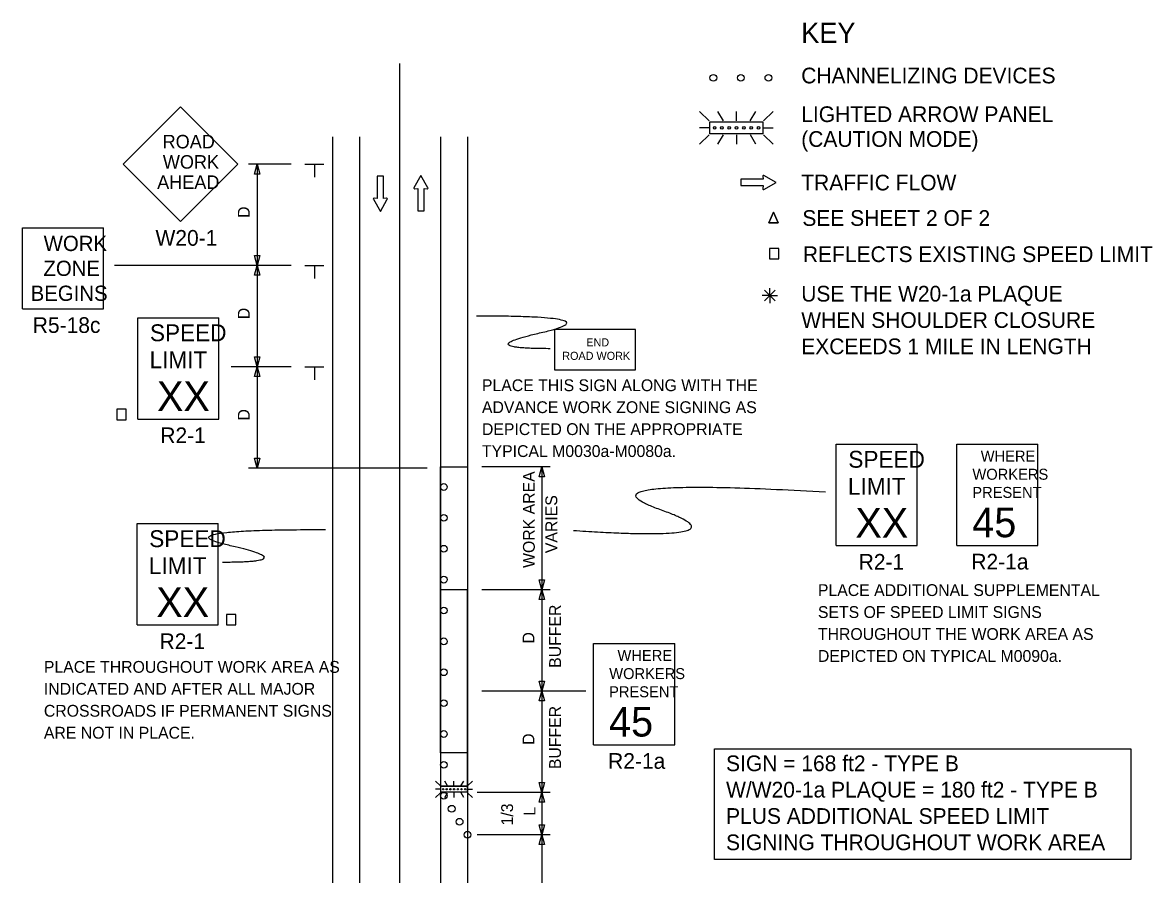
# Model space of a CAD drawing. Extents: x 16750 to 18472, y 7218 to 8205.
# Drawn here: x 16760 to 17429, y 7700 to 8205 of the extents above; entities that cross this region are included whole.
import ezdxf

# ---------------------------------------------------------------- set-up
doc = ezdxf.new("R2010")
doc.units = 0
for name, color, linetype in [('Level 6', 7, 'Continuous'), ('MT_SCRATCH_LEVEL_E', 7, 'Continuous'), ('PAVT_EDGE_EX', 7, 'Continuous'), ('TRAFFIC_SIGNS_PR', 7, 'Continuous'), ('TYPICAL_TEXT_DIMEN_EX', 7, 'Continuous'), ('TYPICAL_TEXT_DIMEN_PR', 7, 'Continuous')]:
    doc.layers.add(name, color=color, linetype=linetype)

msp = doc.modelspace()

# ---------------------------------------------------------------- linework, layer by layer
at = {"layer": 'Level 6'}
for p, q in [((17313.03, 7955.14), (17361.03, 7955.14)), ((17313.03, 7895.14), (17313.03, 7955.14)), ((17361.03, 7895.14), (17361.03, 7955.14)), ((17313.03, 7895.14), (17361.03, 7895.14)), ((17097.89, 7837.09), (17145.89, 7837.09)), ((17097.89, 7777.09), (17097.89, 7837.09)), ((17145.89, 7777.09), (17145.89, 7837.09)), ((17097.89, 7777.09), (17145.89, 7777.09))]:
    msp.add_line(p, q, dxfattribs=at)
for points in [[(17204.47, 8092.37), (17201.67, 8086.2)], [(17201.67, 8086.2), (17204.47, 8092.37)], [(17207.26, 8086.2), (17204.47, 8092.37)], [(17204.47, 8092.37), (17207.26, 8086.2)], [(17201.67, 8086.2), (17207.26, 8086.2)], [(17207.26, 8086.2), (17201.67, 8086.2)]]:
    msp.add_lwpolyline(points, dxfattribs=at)
for points in [[(17202.01, 8064.76), (17207.6, 8064.76), (17207.6, 8070.93), (17202.01, 8070.93)], [(16815.46, 7969.56), (16821.05, 7969.56), (16821.05, 7975.73), (16815.46, 7975.73)], [(16880.44, 7848.01), (16886.04, 7848.01), (16886.04, 7854.18), (16880.44, 7854.18)]]:
    msp.add_lwpolyline(points, close=True, dxfattribs=at)
at = {"layer": 'MT_SCRATCH_LEVEL_E'}
for p, q in [((16973.41, 8113.8), (16969.67, 8113.8)), ((16969.67, 8113.8), (16969.67, 8100.54)), ((16973.41, 8113.8), (16969.67, 8113.8)), ((16969.67, 8113.8), (16969.67, 8100.54)), ((16973.41, 8100.54), (16973.41, 8113.8)), ((16973.41, 8100.54), (16973.41, 8113.8)), ((16995.57, 8114.17), (16991.46, 8106.93)), ((16995.57, 8114.17), (16991.46, 8106.93)), ((16999.72, 8106.93), (16995.57, 8114.17)), ((16999.72, 8106.93), (16995.57, 8114.17)), ((17198.4, 8111.93), (17185.15, 8111.93)), ((17185.15, 8111.93), (17185.15, 8108.19)), ((17198.4, 8111.93), (17185.15, 8111.93)), ((17185.15, 8111.93), (17185.15, 8108.19)), ((17198.09, 8113.71), (17198.4, 8111.93)), ((17198.09, 8113.71), (17198.4, 8111.93)), ((17206.01, 8110.08), (17198.77, 8114.19)), ((17206.01, 8110.08), (17198.77, 8114.19)), ((16991.94, 8106.24), (16993.72, 8106.56)), ((16991.94, 8106.24), (16993.72, 8106.56)), ((16993.72, 8106.56), (16993.72, 8093.3)), ((16993.72, 8106.56), (16993.72, 8093.3)), ((16997.46, 8093.3), (16997.46, 8106.56)), ((16997.46, 8106.56), (16999.24, 8106.24)), ((16997.46, 8093.3), (16997.46, 8106.56)), ((16997.46, 8106.56), (16999.24, 8106.24)), ((17185.15, 8108.19), (17198.4, 8108.19)), ((17185.15, 8108.19), (17198.4, 8108.19)), ((17198.4, 8108.19), (17198.09, 8106.41)), ((17198.4, 8108.19), (17198.09, 8106.41)), ((17198.77, 8105.93), (17206.01, 8110.08)), ((17198.77, 8105.93), (17206.01, 8110.08)), ((16967.42, 8100.17), (16971.56, 8092.93)), ((16967.42, 8100.17), (16971.56, 8092.93)), ((16969.67, 8100.54), (16967.9, 8100.85)), ((16969.67, 8100.54), (16967.9, 8100.85)), ((16971.56, 8092.93), (16975.67, 8100.17)), ((16971.56, 8092.93), (16975.67, 8100.17)), ((16975.19, 8100.85), (16973.41, 8100.54)), ((16975.19, 8100.85), (16973.41, 8100.54)), ((16993.72, 8093.3), (16997.46, 8093.3)), ((16993.72, 8093.3), (16997.46, 8093.3))]:
    msp.add_line(p, q, dxfattribs=at)
for centre, start, end in [((17198.55, 8113.78), 60.42484, 189.96381), ((17198.55, 8113.78), 60.42484, 189.96381), ((16991.87, 8106.7), 150.42484, 279.96381), ((16991.87, 8106.7), 150.42484, 279.96381), ((16999.31, 8106.7), 260.03619, 29.77312), ((16999.31, 8106.7), 260.03619, 29.77312), ((17198.55, 8106.34), 170.03619, 299.77312), ((17198.55, 8106.34), 170.03619, 299.77312), ((16967.82, 8100.39), 80.03619, 209.77312), ((16967.82, 8100.39), 80.03619, 209.77312), ((16975.27, 8100.39), 330.42484, 99.96381), ((16975.27, 8100.39), 330.42484, 99.96381)]:
    msp.add_arc(centre, 0.463, start, end, dxfattribs=at)
at = {"layer": 'PAVT_EDGE_EX'}
for p, q in [((16983.15, 7383.56), (16983.15, 8180.56)), ((16943.15, 8137.01), (16943.15, 7401.86)), ((16959.15, 8137.01), (16959.15, 7401.86)), ((17007.15, 8137.01), (17007.15, 7401.86)), ((17023.15, 8137.01), (17023.15, 7401.86)), ((17007.15, 7772.28), (17007.15, 7941.6)), ((17007.15, 7941.6), (17023.15, 7941.6)), ((17023.15, 7941.6), (17023.15, 7772.28)), ((17023.15, 7868.84), (17007.15, 7868.84)), ((17007.15, 7868.84), (17007.15, 7752.58)), ((17023.15, 7752.58), (17023.15, 7868.84)), ((17023.15, 7772.28), (17007.15, 7772.28)), ((17007.15, 7752.58), (17023.15, 7752.58))]:
    msp.add_line(p, q, dxfattribs=at)
for points in [[(16983.15, 8101.86), (16983.15, 8126.86)], [(16983.15, 8001.86), (16983.15, 8026.86)], [(16983.15, 7901.86), (16983.15, 7926.86)], [(16983.15, 7801.86), (16983.15, 7826.86)], [(16983.15, 7701.86), (16983.15, 7726.86)]]:
    msp.add_lwpolyline(points, dxfattribs=at)
at = {"layer": 'TRAFFIC_SIGNS_PR'}
for p, q in [((16853.15, 8154.77), (16819.21, 8120.83)), ((16887.09, 8120.83), (16853.15, 8154.77)), ((17160.6, 8152.13), (17166.24, 8146.49)), ((17174.78, 8146.49), (17171.52, 8152.13)), ((17182.41, 8146.49), (17182.41, 8152.13)), ((17190.68, 8146.49), (17193.93, 8152.13)), ((17198.58, 8146.49), (17204.22, 8152.13)), ((17166.24, 8142.43), (17160.6, 8142.43)), ((17160.6, 8132.73), (17166.24, 8138.36)), ((17169.51, 8142.43), (17169.51, 8142.43)), ((17171.47, 8132.72), (17174.72, 8138.36)), ((17173.86, 8142.43), (17173.86, 8142.43)), ((17178.21, 8142.43), (17178.21, 8142.43)), ((17182.41, 8138.36), (17182.41, 8132.72)), ((17182.56, 8142.43), (17182.56, 8142.43)), ((17186.9, 8142.43), (17186.9, 8142.43)), ((17193.98, 8132.72), (17190.73, 8138.36)), ((17191.25, 8142.43), (17191.25, 8142.43)), ((17195.6, 8142.43), (17195.6, 8142.43)), ((17198.58, 8142.43), (17204.22, 8142.43)), ((17198.58, 8138.36), (17204.22, 8132.72)), ((16819.21, 8120.83), (16853.15, 8086.88)), ((16853.15, 8086.88), (16887.09, 8120.83)), ((16759.63, 8035.25), (16759.63, 8083.25)), ((16759.63, 8083.25), (16807.63, 8083.25)), ((16807.63, 8035.25), (16807.63, 8083.25)), ((16759.63, 8035.25), (16807.63, 8035.25)), ((16827.86, 8029.97), (16875.86, 8029.97)), ((16827.86, 7969.97), (16827.86, 8029.97)), ((16875.86, 7969.97), (16875.86, 8029.97)), ((16827.86, 7969.97), (16875.86, 7969.97)), ((17241.54, 7955.03), (17289.54, 7955.03)), ((17241.54, 7895.03), (17241.54, 7955.03)), ((17289.54, 7895.03), (17289.54, 7955.03)), ((17009.15, 7929.7), (17009.15, 7929.7)), ((17009.15, 7911.41), (17009.15, 7911.41)), ((16827.43, 7908.01), (16875.43, 7908.01)), ((16827.43, 7848.01), (16827.43, 7908.01)), ((16875.43, 7848.01), (16875.43, 7908.01)), ((17009.15, 7893.13), (17009.15, 7893.13)), ((17241.54, 7895.03), (17289.54, 7895.03)), ((17009.15, 7874.84), (17009.15, 7874.84)), ((16827.43, 7848.01), (16875.43, 7848.01)), ((17023.15, 7772.28), (17007.15, 7772.28)), ((17004.26, 7755.53), (17007.08, 7752.71)), ((17007.08, 7750.68), (17004.26, 7750.68)), ((17023.15, 7752.58), (17007.15, 7752.58)), ((17008.72, 7750.68), (17008.72, 7750.68)), ((17011.35, 7752.71), (17009.72, 7755.53)), ((17010.9, 7750.68), (17010.9, 7750.68)), ((17013.07, 7750.68), (17013.07, 7750.68)), ((17015.17, 7752.71), (17015.17, 7755.53)), ((17015.24, 7750.68), (17015.24, 7750.68)), ((17017.42, 7750.68), (17017.42, 7750.68)), ((17019.3, 7752.71), (17020.93, 7755.53)), ((17019.59, 7750.68), (17019.59, 7750.68)), ((17021.76, 7750.68), (17021.76, 7750.68)), ((17023.25, 7752.71), (17026.08, 7755.53)), ((17023.25, 7750.68), (17026.08, 7750.68)), ((17004.26, 7745.83), (17007.08, 7748.64)), ((17009.7, 7745.82), (17011.33, 7748.64)), ((17015.17, 7748.64), (17015.17, 7745.82)), ((17020.96, 7745.82), (17019.33, 7748.64)), ((17023.25, 7748.64), (17026.08, 7745.82))]:
    msp.add_line(p, q, dxfattribs=at)
for points in [[(17198.12, 8138.83), (17166.7, 8138.83), (17166.7, 8146.03), (17198.12, 8146.03)], [(17074.78, 7999.07), (17122.78, 7999.07), (17122.78, 8023.07), (17074.78, 8023.07)], [(17023.02, 7748.88), (17007.32, 7748.88), (17007.32, 7752.48), (17023.02, 7752.48)]]:
    msp.add_lwpolyline(points, close=True, dxfattribs=at)
for centre, radius in [((17168.8, 8172), 2), ((17185.1, 8172), 2), ((17201.4, 8172), 2), ((17169.55, 8142.43), 0.758), ((17173.86, 8142.43), 0.758), ((17178.21, 8142.43), 0.758), ((17182.55, 8142.43), 0.758), ((17186.9, 8142.43), 0.758), ((17191.25, 8142.43), 0.758), ((17195.6, 8142.43), 0.758), ((17009.15, 7929.7), 2), ((17009.15, 7911.41), 2), ((17009.15, 7893.13), 2), ((17009.15, 7874.84), 2), ((17009.15, 7856.55), 2), ((17009.15, 7838.27), 2), ((17009.15, 7819.98), 2), ((17009.15, 7801.7), 2), ((17009.15, 7783.41), 2), ((17009.15, 7765.13), 2), ((17008.74, 7750.68), 0.379), ((17010.89, 7750.68), 0.379), ((17013.07, 7750.68), 0.379), ((17015.24, 7750.68), 0.379), ((17017.42, 7750.68), 0.379), ((17019.59, 7750.68), 0.379), ((17021.76, 7750.68), 0.379), ((17009.14, 7746.84), 2), ((17009.15, 7746.84), 2), ((17013.81, 7739.14), 2), ((17018.48, 7731.45), 2), ((17023.15, 7723.75), 2)]:
    msp.add_circle(centre, radius, dxfattribs=at)
for points in [[(17072.14, 8011.62), (17024.9, 8011.62), (17109.92, 8030.96), (17028.44, 8030.96)], [(17085.99, 7903.97), (17191.91, 7896.9), (17082.67, 7935.63), (17235.15, 7926.81)], [(16877.98, 7885.25), (16925.21, 7885.25), (16840.19, 7904.6), (16939, 7904.48)]]:
    msp.add_open_spline(points, degree=2, dxfattribs=at)
at = {"layer": 'TYPICAL_TEXT_DIMEN_PR'}
for p, q in [((16918.8, 8120.93), (16893.52, 8120.93)), ((16896.95, 8115.07), (16898.52, 8120.93)), ((16898.52, 8120.93), (16900.09, 8115.07)), ((16898.52, 8120.93), (16898.52, 8060.93)), ((16926.84, 8120.93), (16938.09, 8120.93)), ((16932.46, 8120.93), (16932.46, 8113.15)), ((16898.52, 8115.07), (16896.95, 8115.07)), ((16900.09, 8115.07), (16898.52, 8115.07)), ((16898.52, 8060.93), (16896.95, 8066.79)), ((16896.95, 8066.79), (16898.52, 8066.79)), ((16898.52, 8066.79), (16900.09, 8066.79)), ((16900.09, 8066.79), (16898.52, 8060.93)), ((16918.8, 8060.93), (16814.05, 8060.93)), ((16896.95, 8055.07), (16898.52, 8060.93)), ((16898.52, 8060.93), (16900.09, 8055.07)), ((16898.52, 8060.93), (16898.52, 8000.93)), ((16926.84, 8060.93), (16938.09, 8060.93)), ((16932.46, 8060.93), (16932.46, 8053.15)), ((16898.52, 8055.07), (16896.95, 8055.07)), ((16900.09, 8055.07), (16898.52, 8055.07)), ((17199.06, 8046.25), (17205.44, 8039.87)), ((17205.44, 8046.25), (17199.06, 8039.87)), ((17202.25, 8043.06), (17202.25, 8047.51)), ((17202.25, 8043.06), (17197.72, 8043.06)), ((17202.25, 8043.06), (17205.44, 8043.06)), ((17202.25, 8043.06), (17206.73, 8043.06)), ((17202.25, 8043.06), (17202.25, 8038.56)), ((16898.52, 8000.93), (16896.95, 8006.79)), ((16896.95, 8006.79), (16898.52, 8006.79)), ((16898.52, 8006.79), (16900.09, 8006.79)), ((16900.09, 8006.79), (16898.52, 8000.93)), ((16918.8, 8000.93), (16883.17, 8000.93)), ((16896.95, 7995.07), (16898.52, 8000.93)), ((16898.52, 8000.93), (16900.09, 7995.07)), ((16898.52, 8000.55), (16898.52, 7940.93)), ((16926.84, 8000.93), (16938.09, 8000.93)), ((16932.46, 8000.93), (16932.46, 7993.15)), ((16898.52, 7995.07), (16896.95, 7995.07)), ((16900.09, 7995.07), (16898.52, 7995.07)), ((16898.52, 7940.93), (16896.95, 7946.79)), ((16896.95, 7946.79), (16898.52, 7946.79)), ((16898.52, 7940.93), (16896.95, 7946.79)), ((16896.95, 7946.79), (16898.52, 7946.79)), ((16898.52, 7946.79), (16900.09, 7946.79)), ((16900.09, 7946.79), (16898.52, 7940.93)), ((16898.52, 7946.79), (16900.09, 7946.79)), ((16900.09, 7946.79), (16898.52, 7940.93)), ((16999.22, 7940.93), (16893.52, 7940.93)), ((17072.15, 7941.6), (17031.74, 7941.6)), ((17065.58, 7935.74), (17067.15, 7941.6)), ((17067.15, 7941.6), (17067.15, 7868.84)), ((17067.15, 7941.6), (17068.73, 7935.74)), ((17067.15, 7935.74), (17065.58, 7935.74)), ((17068.73, 7935.74), (17067.15, 7935.74)), ((17067.15, 7868.84), (17065.58, 7874.7)), ((17065.58, 7874.7), (17067.15, 7874.7)), ((17067.15, 7874.7), (17068.73, 7874.7)), ((17068.73, 7874.7), (17067.15, 7868.84)), ((17072.15, 7868.84), (17031.74, 7868.84)), ((17065.58, 7862.98), (17067.15, 7868.84)), ((17067.15, 7868.84), (17068.73, 7862.98)), ((17067.15, 7868.84), (17067.15, 7808.84)), ((17067.15, 7862.98), (17065.58, 7862.98)), ((17068.73, 7862.98), (17067.15, 7862.98)), ((17067.15, 7808.84), (17065.58, 7814.7)), ((17065.58, 7814.7), (17067.15, 7814.7)), ((17067.15, 7814.7), (17068.73, 7814.7)), ((17068.73, 7814.7), (17067.15, 7808.84)), ((17093.23, 7808.84), (17031.74, 7808.84)), ((17065.58, 7802.98), (17067.15, 7808.84)), ((17067.15, 7808.84), (17068.73, 7802.98)), ((17067.15, 7808.84), (17067.15, 7748.84)), ((17067.15, 7802.98), (17065.58, 7802.98)), ((17068.73, 7802.98), (17067.15, 7802.98)), ((17067.15, 7748.84), (17065.58, 7754.7)), ((17065.58, 7754.7), (17067.15, 7754.7)), ((17067.15, 7754.7), (17068.73, 7754.7)), ((17068.73, 7754.7), (17067.15, 7748.84)), ((17072.15, 7748.84), (17028.88, 7748.84)), ((17065.58, 7742.98), (17067.15, 7748.84)), ((17067.15, 7748.84), (17067.15, 7723.75)), ((17067.15, 7748.84), (17068.73, 7742.98)), ((17067.15, 7742.98), (17065.58, 7742.98)), ((17068.73, 7742.98), (17067.15, 7742.98)), ((17067.15, 7723.75), (17065.58, 7729.61)), ((17065.58, 7729.61), (17067.15, 7729.61)), ((17067.15, 7729.61), (17068.73, 7729.61)), ((17068.73, 7729.61), (17067.15, 7723.75)), ((17072.15, 7723.75), (17028.88, 7723.75)), ((17065.58, 7717.89), (17067.15, 7723.75)), ((17067.15, 7723.75), (17068.73, 7717.89)), ((17067.15, 7723.75), (17067.15, 7664.3)), ((17067.15, 7717.89), (17065.58, 7717.89)), ((17068.73, 7717.89), (17067.15, 7717.89))]:
    msp.add_line(p, q, dxfattribs=at)
msp.add_lwpolyline([(17169.41, 7774.54), (17416, 7774.54), (17416, 7709.1), (17169.41, 7709.1)], close=True, dxfattribs=at)

# ---------------------------------------------------------------- texts
at = {"layer": 'Level 6'}
for s, height, p in [('45', 17.538, (17322.16, 7899.96)), ('R2-1a', 9.3, (17321.6, 7880.84)), ('45', 17.538, (17107.02, 7781.91)), ('R2-1a', 9.3, (17106.45, 7762.79))]:
    msp.add_text(s, height=height, dxfattribs=at).set_placement(p)
at = {"layer": 'TRAFFIC_SIGNS_PR'}
for s, height, p in [('ROAD', 8, (16842.58, 8130.24)), ('WORK', 8, (16842.72, 8118.24)), ('AHEAD', 8, (16839.35, 8106.24)), ('WORK', 9.021, (16772.13, 8069.46)), ('W20-1', 9.3, (16838.37, 8072.59)), ('ZONE', 9.021, (16771.99, 8054.7)), ('BEGINS', 9.021, (16764.4, 8039.93)), ('R5-18c', 9.3, (16765.65, 8020.95)), ('SPEED', 10, (16835.07, 8016.04)), ('END', 4.789, (17093.53, 8012.98)), ('LIMIT', 10, (16834.87, 8000.04)), ('ROAD WORK', 4.789, (17079.29, 8005)), ('XX', 17.538, (16839.25, 7974.66)), ('PLACE THIS SIGN ALONG WITH THE', 7, (17031.72, 7986.46)), ('ADVANCE WORK ZONE SIGNING AS', 7, (17031.72, 7973.46)), ('R2-1', 9.3, (16841.21, 7955.67)), ('DEPICTED ON THE APPROPRIATE', 7, (17031.72, 7960.46)), ('TYPICAL M0030a-M0080a.', 7, (17031.72, 7947.46)), ('SPEED', 10, (17248.75, 7941.11)), ('WHERE', 6.5, (17327.17, 7944.75)), ('WORKERS', 6.5, (17322.26, 7934)), ('LIMIT', 10, (17248.54, 7925.11)), ('PRESENT', 6.5, (17322.18, 7923.25)), ('XX', 17.538, (17252.93, 7899.73)), ('SPEED', 10, (16834.64, 7894.09)), ('LIMIT', 10, (16834.43, 7878.09)), ('R2-1', 9.3, (17254.88, 7880.73)), ('XX', 17.538, (16838.82, 7852.71)), ('PLACE ADDITIONAL SUPPLEMENTAL', 7, (17230.73, 7865.13)), ('SETS OF SPEED LIMIT SIGNS', 7, (17230.73, 7852.13)), ('THROUGHOUT THE WORK AREA AS', 7, (17230.73, 7839.13)), ('R2-1', 9.3, (16840.77, 7833.71)), ('WHERE', 6.5, (17112.02, 7826.69)), ('DEPICTED ON TYPICAL M0090a.', 7, (17230.73, 7826.13)), ('PLACE THROUGHOUT WORK AREA AS', 7, (16772.25, 7819.66)), ('WORKERS', 6.5, (17107.12, 7815.94)), ('INDICATED AND AFTER ALL MAJOR', 7, (16772.25, 7806.66)), ('PRESENT', 6.5, (17107.03, 7805.19)), ('CROSSROADS IF PERMANENT SIGNS', 7, (16772.25, 7793.66)), ('ARE NOT IN PLACE.', 7, (16772.25, 7780.66))]:
    msp.add_text(s, height=height, dxfattribs=at).set_placement(p)
at = {"layer": 'TYPICAL_TEXT_DIMEN_EX'}
for s, height, p in [('KEY', 12, (17220.86, 8192.74)), ('CHANNELIZING DEVICES', 9.3, (17220.86, 8168.74)), ('LIGHTED ARROW PANEL', 9.3, (17220.86, 8145.84)), ('(CAUTION MODE)', 9.3, (17220.86, 8131.14)), ('TRAFFIC FLOW', 9.3, (17220.86, 8105.34)), ('SEE SHEET 2 OF 2', 9.3, (17221.5, 8084.36)), ('REFLECTS EXISTING SPEED LIMIT', 9.3, (17221.84, 8062.92)), ('USE THE W20-1a PLAQUE', 9.3, (17220.86, 8039.53)), ('WHEN SHOULDER CLOSURE', 9.3, (17220.86, 8023.93)), ('EXCEEDS 1 MILE IN LENGTH', 9.3, (17220.86, 8008.33))]:
    msp.add_text(s, height=height, dxfattribs=at).set_placement(p)
at = {"layer": 'TYPICAL_TEXT_DIMEN_PR'}
for s, p in [('D', (16894.14, 8089.07)), ('D', (16894.14, 8029.07)), ('D', (16894.14, 7969.07)), ('WORK AREA', (17063.03, 7881.77)), ('VARIES', (17076.33, 7890.5)), ('BUFFER', (17078.54, 7822.62)), ('D', (17062.78, 7836.98)), ('BUFFER', (17078.54, 7762.62)), ('D', (17062.78, 7776.98)), ('1/3', (17050.14, 7729.26)), ('L', (17063.44, 7735.06))]:
    msp.add_text(s, height=7, rotation=90, dxfattribs=at).set_placement(p)
for s, p in [('SIGN = 168 ft2 - TYPE B', (17176.34, 7761.4)), ('W/W20-1a PLAQUE = 180 ft2 - TYPE B', (17176.34, 7745.8)), ('PLUS ADDITIONAL SPEED LIMIT', (17176.34, 7730.2)), ('SIGNING THROUGHOUT WORK AREA', (17176.34, 7714.6))]:
    msp.add_text(s, height=9.3, dxfattribs=at).set_placement(p)

doc.saveas('drawing.dxf')
